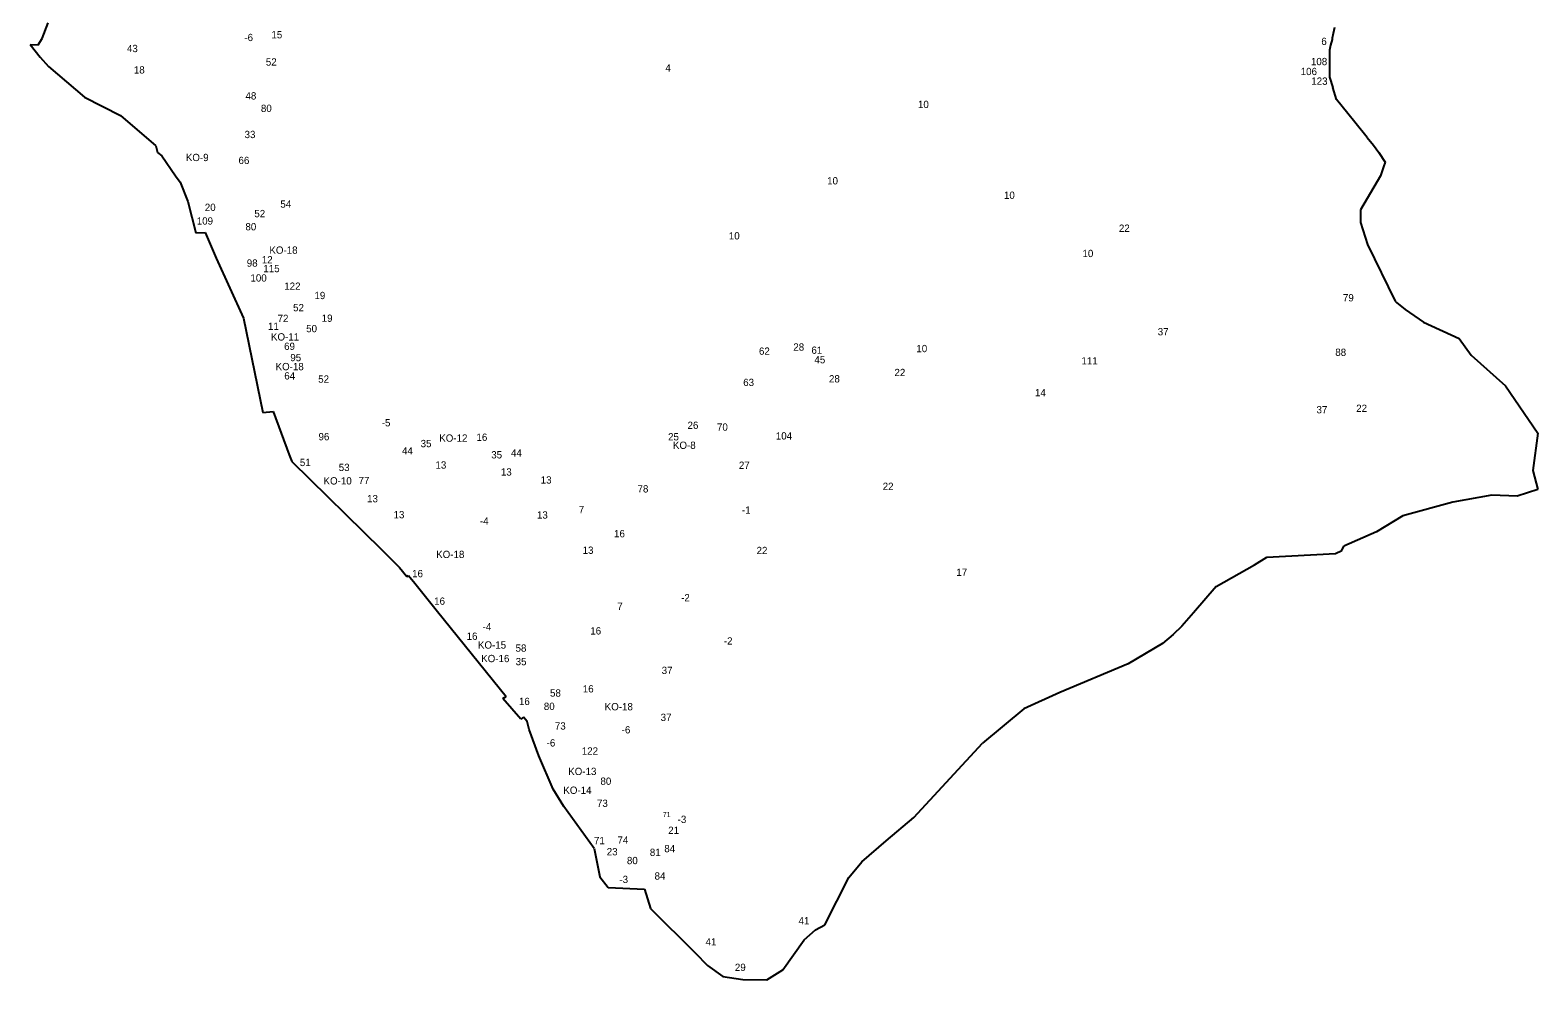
# Model space of a CAD drawing. Extents: x -782710 to -781421, y -973233 to -970222.
# Drawn here: x -782647 to -781456, y -973233 to -972483 of the extents above; entities that cross this region are included whole.
import ezdxf

# ---------------------------------------------------------------- set-up
doc = ezdxf.new("R2010")
doc.units = 0
doc.layers.add('Vrstva 13', color=7, linetype='Continuous')
doc.layers.add('Vrstva 24', color=7, linetype='Continuous')

msp = doc.modelspace()

# ---------------------------------------------------------------- linework, layer by layer
at = {"layer": 'Vrstva 13'}
for p, q in [((-782637.18, -972489.33), (-782632.45, -972476.83)), ((-782640.21, -972494.38), (-782637.18, -972489.33)), ((-781618.58, -972490), (-781619.7, -972494.65)), ((-781618.39, -972488.95), (-781618.58, -972490)), ((-781617.72, -972485.36), (-781618.39, -972488.95)), ((-781616.62, -972480.47), (-781617.72, -972485.36)), ((-782646.55, -972494.05), (-782638.77, -972504.03)), ((-782646.55, -972494.05), (-782640.21, -972494.38)), ((-781619.7, -972494.65), (-781620.66, -972498.48)), ((-781620.66, -972498.48), (-781620.48, -972519.7)), ((-782638.77, -972504.03), (-782632.03, -972511.31)), ((-782632.03, -972511.31), (-782603.52, -972535.58)), ((-781620.48, -972519.7), (-781617.96, -972527.84)), ((-782603.52, -972535.58), (-782575.21, -972550.14)), ((-781614.97, -972537.42), (-781617.96, -972527.84)), ((-781606.19, -972548.57), (-781614.97, -972537.42)), ((-782575.21, -972550.14), (-782547.27, -972573.91)), ((-781600.57, -972555.41), (-781606.19, -972548.57)), ((-781590.8, -972567.5), (-781600.57, -972555.41)), ((-782547.27, -972573.91), (-782545.9, -972579.19)), ((-781590.8, -972567.5), (-781585.92, -972573.48)), ((-781585.92, -972573.48), (-781581.52, -972579.28)), ((-782545.9, -972579.19), (-782542.63, -972581.93)), ((-782542.63, -972581.93), (-782531.88, -972597.68)), ((-781581.52, -972579.28), (-781576.71, -972587.04)), ((-781576.71, -972587.04), (-781577.898, -972590.558)), ((-782531.88, -972597.68), (-782528.17, -972602.79)), ((-781580.21, -972597.68), (-781596.14, -972624.52)), ((-781577.898, -972590.558), (-781580.21, -972597.68)), ((-782528.17, -972602.79), (-782522.07, -972618.13)), ((-782522.07, -972618.13), (-782515.84, -972642.78)), ((-781596.14, -972624.52), (-781595.98, -972634.6)), ((-781595.98, -972634.6), (-781590.61, -972651.96)), ((-781595.98, -972634.6), (-781595.98, -972634.6)), ((-781595.98, -972634.6), (-781595.98, -972634.6)), ((-782515.84, -972642.78), (-782508.47, -972642.59)), ((-782508.47, -972642.59), (-782499.71, -972662.72)), ((-781590.61, -972651.96), (-781568.62, -972696.7)), ((-782499.71, -972662.72), (-782478.14, -972710.17)), ((-781568.62, -972696.7), (-781567.64, -972697.68)), ((-781567.64, -972697.68), (-781560.89, -972703.25)), ((-781560.89, -972703.25), (-781546.25, -972713.42)), ((-782478.14, -972710.17), (-782462.82, -972784.77)), ((-781546.25, -972713.42), (-781518.23, -972726.16)), ((-781518.23, -972726.16), (-781508.72, -972739.48)), ((-781508.72, -972739.48), (-781481.68, -972763.63)), ((-781481.68, -972763.63), (-781456.04, -972801.1)), ((-782462.82, -972784.77), (-782454.74, -972783.9)), ((-782454.74, -972783.9), (-782442.08, -972818.15)), ((-781456.04, -972801.1), (-781459.94, -972830.54)), ((-782442.08, -972818.15), (-782440.03, -972823.43)), ((-782440.03, -972823.43), (-782369, -972892.88)), ((-781459.94, -972830.54), (-781456.12, -972845.6)), ((-781456.12, -972845.6), (-781472.5, -972850.75)), ((-781523.26, -972855.53), (-781562.54, -972866.2)), ((-781492.42, -972849.88), (-781523.26, -972855.53)), ((-781472.5, -972850.75), (-781492.42, -972849.88)), ((-781562.54, -972866.2), (-781583.54, -972879.03)), ((-781583.54, -972879.03), (-781609.266, -972890.22)), ((-782369, -972892.88), (-782354.87, -972907.08)), ((-781669.95, -972898.86), (-781615.88, -972895.9)), ((-781615.88, -972895.9), (-781610.73, -972893.69)), ((-781610.73, -972893.69), (-781609.266, -972890.22)), ((-782354.87, -972907.08), (-782349.09, -972914.28)), ((-781710.05, -972922.13), (-781679.78, -972905.1)), ((-781679.78, -972905.1), (-781669.95, -972898.86)), ((-782349.09, -972914.28), (-782347.91, -972913.46)), ((-782347.91, -972913.46), (-782342.77, -972919.56)), ((-782342.77, -972919.56), (-782324.85, -972941.78)), ((-781710.05, -972922.13), (-781727.83, -972942.97)), ((-782324.85, -972941.78), (-782270.79, -973009)), ((-781727.83, -972942.97), (-781737.17, -972953.47)), ((-781737.17, -972953.47), (-781743.96, -972959.96)), ((-781752.35, -972967.16), (-781779.48, -972983.21)), ((-781743.96, -972959.96), (-781752.35, -972967.16)), ((-781779.48, -972983.21), (-781833.52, -973005.9)), ((-782273.19, -973010.58), (-782270.79, -973009)), ((-782259.08, -973026.8), (-782273.19, -973010.58)), ((-781833.52, -973005.9), (-781861.8, -973018.64)), ((-782256.93, -973025.25), (-782259.08, -973026.8)), ((-782254.07, -973028.72), (-782256.93, -973025.25)), ((-781861.8, -973018.64), (-781894.63, -973045.84)), ((-782252.5, -973035.05), (-782254.07, -973028.72)), ((-782244.85, -973055.91), (-782252.5, -973035.05)), ((-781948.75, -973104.64), (-781894.63, -973045.84)), ((-782233.65, -973082.15), (-782244.85, -973055.91)), ((-782225.08, -973095.91), (-782233.65, -973082.15)), ((-782201.22, -973129.08), (-782225.08, -973095.91)), ((-781970.54, -973123.11), (-781948.75, -973104.64)), ((-782201.22, -973129.08), (-782196.68, -973151.41)), ((-781989.89, -973139.49), (-781970.54, -973123.11)), ((-781999.98, -973152.06), (-781989.89, -973139.49)), ((-782196.68, -973151.41), (-782190.03, -973159.88)), ((-782019.07, -973189.42), (-781999.98, -973152.06)), ((-782190.03, -973159.88), (-782161.52, -973161.16)), ((-782161.52, -973161.16), (-782156.78, -973176.56)), ((-782156.78, -973176.56), (-782121.53, -973211.46)), ((-782035.47, -973201.26), (-782026.54, -973193.15)), ((-782026.54, -973193.15), (-782019.07, -973189.42)), ((-782052.14, -973224.77), (-782035.47, -973201.26)), ((-782121.53, -973211.46), (-782111.79, -973221.48)), ((-782111.79, -973221.48), (-782099.68, -973230.05)), ((-782064.8, -973232.79), (-782052.14, -973224.77)), ((-782099.68, -973230.05), (-782083.83, -973232.6)), ((-782083.83, -973232.6), (-782064.8, -973232.79))]:
    msp.add_line(p, q, dxfattribs=at)

# ---------------------------------------------------------------- texts
at = {"layer": 'Vrstva 24'}
for s, height, p in [('-6', 5.76, (-782477.403, -972491.3)), ('15', 5.76, (-782456.045, -972489.132)), ('6', 5.76, (-781627.006, -972494.402)), ('43', 5.76, (-782570.108, -972500.032)), ('18', 5.76, (-782564.665, -972516.912)), ('52', 5.76, (-782460.453, -972510.652)), ('4', 5.76, (-782144.958, -972515.382)), ('106', 5.76, (-781643.285, -972518.172)), ('108', 5.76, (-781635.222, -972510.332)), ('123', 5.76, (-781634.945, -972525.812)), ('48', 5.76, (-782476.528, -972537.432)), ('10', 5.76, (-781945.522, -972544.192)), ('80', 5.76, (-782464.329, -972547.292)), ('33', 5.76, (-782477.243, -972567.932)), ('KO-9', 5.76, (-782523.615, -972586.09)), ('66', 5.76, (-782482.029, -972588.412)), ('10', 5.76, (-782017.232, -972604.532)), ('10', 5.76, (-781877.612, -972615.922)), ('20', 5.76, (-782508.649, -972625.492)), ('54', 5.76, (-782448.978, -972622.932)), ('109', 5.76, (-782514.995, -972636.252)), ('52', 5.76, (-782469.523, -972630.412)), ('80', 5.76, (-782476.569, -972640.792)), ('10', 5.76, (-782094.842, -972647.992)), ('22', 5.76, (-781786.843, -972641.962)), ('KO-18', 5.76, (-782457.644, -972659.27)), ('10', 5.76, (-781815.612, -972661.912)), ('98', 5.76, (-782475.506, -972669.502)), ('12', 5.76, (-782463.635, -972666.872)), ('115', 5.76, (-782462.418, -972673.842)), ('100', 5.76, (-782472.609, -972681.242)), ('122', 5.76, (-782445.915, -972687.772)), ('19', 5.76, (-782422.059, -972695.102)), ('79', 5.76, (-781609.958, -972696.902)), ('52', 5.76, (-782438.933, -972704.692)), ('11', 5.76, (-782458.708, -972719.402)), ('72', 5.76, (-782451.185, -972713.222)), ('50', 5.76, (-782428.599, -972721.262)), ('19', 5.76, (-782416.359, -972713.042)), ('37', 5.76, (-781756.185, -972723.712)), ('KO-11', 5.76, (-782456.396, -972727.8)), ('69', 5.76, (-782446.039, -972735.272)), ('28', 5.76, (-782043.933, -972735.812)), ('95', 5.76, (-782441.116, -972744.152)), ('62', 5.76, (-782071.066, -972739.082)), ('61', 5.76, (-782029.649, -972738.302)), ('45', 5.76, (-782027.258, -972745.782)), ('10', 5.76, (-781946.792, -972737.022)), ('111', 5.76, (-781816.421, -972746.722)), ('88', 5.76, (-781615.983, -972739.962)), ('KO-18', 5.76, (-782452.764, -972751.27)), ('64', 5.76, (-782445.892, -972758.602)), ('22', 5.76, (-781964.083, -972755.942)), ('52', 5.76, (-782419.103, -972761.142)), ('63', 5.76, (-782083.506, -972763.782)), ('28', 5.76, (-782015.773, -972760.922)), ('14', 5.76, (-781853.101, -972771.842)), ('37', 5.76, (-781630.805, -972785.322)), ('22', 5.76, (-781599.473, -972784.232)), ('96', 5.76, (-782418.859, -972806.612)), ('-5', 5.76, (-782368.93, -972795.64)), ('16', 5.76, (-782294.109, -972807.062)), ('25', 5.76, (-782142.843, -972806.712)), ('26', 5.76, (-782127.466, -972797.642)), ('70', 5.76, (-782104.211, -972799.032)), ('104', 5.76, (-782057.747, -972806.002)), ('44', 5.76, (-782352.924, -972817.812)), ('35', 5.76, (-782338.223, -972812.062)), ('KO-12', 5.76, (-782323.524, -972807.72)), ('KO-8', 5.76, (-782139.001, -972813.41)), ('51', 5.76, (-782433.595, -972826.992)), ('53', 5.76, (-782402.883, -972830.892)), ('13', 5.76, (-782326.515, -972829.002)), ('35', 5.76, (-782282.463, -972820.942)), ('44', 5.76, (-782266.864, -972819.502)), ('27', 5.76, (-782086.915, -972829.192)), ('KO-10', 5.76, (-782414.88, -972841.53)), ('77', 5.76, (-782387.217, -972841.242)), ('13', 5.76, (-782274.845, -972834.482)), ('13', 5.76, (-782243.425, -972840.812)), ('78', 5.76, (-782166.945, -972847.832)), ('22', 5.76, (-781973.363, -972845.862)), ('13', 5.76, (-782380.505, -972855.582)), ('7', 5.76, (-782213.335, -972864.232)), ('-1', 5.76, (-782084.492, -972864.6)), ('13', 5.76, (-782359.625, -972868.242)), ('-4', 5.76, (-782291.375, -972873.23)), ('13', 5.76, (-782246.375, -972868.452)), ('16', 5.76, (-782185.499, -972883.222)), ('KO-18', 5.76, (-782325.944, -972899.62)), ('13', 5.76, (-782210.305, -972896.302)), ('22', 5.76, (-782072.953, -972896.522)), ('17', 5.76, (-781915.207, -972913.742)), ('16', 5.76, (-782344.939, -972914.772)), ('16', 5.76, (-782327.539, -972936.512)), ('-2', 5.76, (-782132.55, -972933.8)), ('7', 5.76, (-782182.965, -972940.602)), ('-4', 5.76, (-782289.265, -972956.78)), ('16', 5.76, (-782204.269, -972960.012)), ('16', 5.76, (-782301.919, -972964.252)), ('KO-15', 5.76, (-782292.974, -972971.17)), ('58', 5.76, (-782263.253, -972973.622)), ('-2', 5.76, (-782098.81, -972967.98)), ('KO-16', 5.76, (-782290.398, -972981.86)), ('35', 5.76, (-782263.193, -972984.282)), ('37', 5.76, (-782147.875, -972991.242)), ('58', 5.76, (-782236.043, -973009.072)), ('16', 5.76, (-782210.169, -973005.802)), ('16', 5.76, (-782260.579, -973015.732)), ('80', 5.76, (-782240.949, -973019.642)), ('KO-18', 5.76, (-782192.884, -973019.9)), ('37', 5.76, (-782148.705, -973028.292)), ('73', 5.76, (-782232.215, -973035.112)), ('-6', 5.76, (-782179.473, -973038.15)), ('-6', 5.76, (-782238.733, -973048.49)), ('122', 5.76, (-782210.975, -973054.902)), ('KO-13', 5.76, (-782221.684, -973071.02)), ('80', 5.76, (-782196.229, -973078.742)), ('KO-14', 5.76, (-782225.54, -973085.89)), ('73', 5.76, (-782198.985, -973096.212)), ('71', 4, (-782146.988, -973104.21)), ('-3', 5.76, (-782135.3, -973108.88)), ('71', 5.76, (-782201.327, -973125.652)), ('74', 5.76, (-782182.781, -973125.222)), ('21', 5.76, (-782142.775, -973117.532)), ('23', 5.76, (-782191.263, -973134.412)), ('81', 5.76, (-782157.225, -973134.952)), ('84', 5.76, (-782145.798, -973131.992)), ('80', 5.76, (-782175.339, -973141.422)), ('-3', 5.76, (-782181.27, -973156.35)), ('84', 5.76, (-782153.498, -973153.632)), ('41', 5.76, (-782039.801, -973188.962)), ('41', 5.76, (-782113.201, -973205.642)), ('29', 5.76, (-782090.076, -973225.762))]:
    msp.add_text(s, height=height, dxfattribs=at).set_placement(p)

doc.saveas('drawing.dxf')
